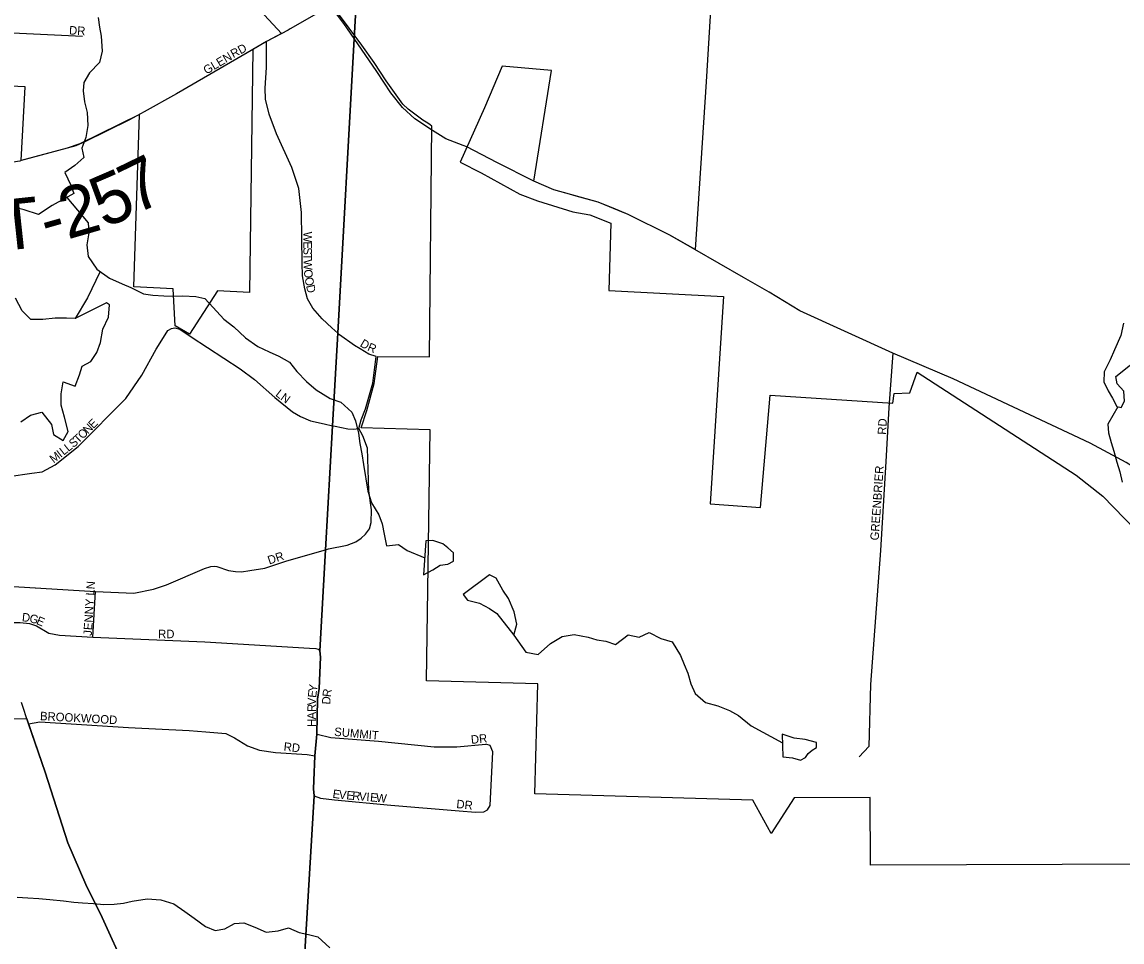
# Model space of a CAD drawing. Extents: x 1759416 to 2214760, y 252598 to 1116833.
# Drawn here: x 1975170 to 1981672, y 856869 to 862305 of the extents above; entities that cross this region are included whole.
import ezdxf

# ---------------------------------------------------------------- set-up
doc = ezdxf.new("R2010")
doc.units = 0
for name, color, linetype in [('GM_X_City_Street', 7, 'Continuous'), ('GM_X_City_Street_Text', 7, 'Continuous'), ('GM_X_Corporation', 7, 'Continuous'), ('GM_X_Minor_Lake', 7, 'Continuous'), ('GM_X_Minor_River', 7, 'Continuous'), ('GM_X_State_Route', 7, 'Continuous'), ('GM_X_Township', 7, 'Continuous'), ('GM_X_Township_Road', 7, 'Continuous'), ('GM_X_Township_Road_Text', 7, 'Continuous'), ('GM_X_Township_Subdivision', 7, 'Continuous'), ('GM_X_Township_Subdivision_Text', 7, 'Continuous')]:
    doc.layers.add(name, color=color, linetype=linetype)

msp = doc.modelspace()

# ---------------------------------------------------------------- linework, layer by layer
at = {"layer": 'GM_X_City_Street'}
for points in [[(1973953.1, 862292.3), (1974040, 862294.5), (1974738, 862257.8), (1975527.8, 862221)], [(1976561.6, 862158.8), (1976083.7, 861881), (1975892.9, 861774.6)], [(1980293.2, 860027.5), (1980293, 860024.4), (1980276.7, 859708.5), (1980244.4, 859182.2), (1980186, 858391.2), (1980175.8, 858023.5), (1980118.3, 857963.8)]]:
    msp.add_lwpolyline(points, dxfattribs=at)
at = {"layer": 'GM_X_Corporation'}
for points in [[(1979325.1, 863774.1), (1979214, 861950.5), (1979148.7, 860960), (1978998.5, 861046.4), (1978752.4, 861168), (1978664.1, 861204.5), (1978575.7, 861241), (1978314.5, 861314), (1978195.4, 861364), (1978300.2, 862018.9), (1978009.2, 862044.1), (1977903, 861797.5), (1977759.1, 861477.3), (1977884.4, 861414.5), (1978113.4, 861287.2), (1978216.3, 861247.5), (1978426.9, 861182.4), (1978527.1, 861165), (1978651.4, 861116.4), (1978637.9, 860718.4), (1979315.7, 860683.9), (1979238.5, 859458.6), (1979535.5, 859436.9), (1979593.2, 860100), (1980317.6, 860053.2), (1980324.8, 860110.9), (1980418.5, 860114.5), (1980461.7, 860237), (1981400.8, 859626.9), (1981558.6, 859504), (1982393.6, 858642)], [(1975947.8, 863054.3), (1976704, 862236.7), (1976615.9, 862190.4), (1976534, 862142.5), (1976515, 860706.8), (1976325.2, 860716.2), (1976159.8, 860460.1), (1976075.7, 860510.4), (1976063.6, 860729), (1975830.9, 860740.8), (1975863.8, 861758.4), (1975511.8, 861584.7), (1975436.8, 861559.6), (1975165.6, 861485.7), (1975189.6, 861922.7), (1973985.8, 861976.4)], [(1981885.6, 857329.1), (1980185.5, 857323.1), (1980184.1, 857723.1), (1979734.1, 857721.5), (1979598.7, 857511.3), (1979488.9, 857707.8), (1978200.9, 857744.3), (1978219.3, 858394.1), (1977561.5, 858412.8), (1977583.2, 859896.1), (1977174.8, 859906.5), (1977208.1, 860010.2), (1977252.1, 860168.8), (1977273, 860329.6), (1977579.4, 860327), (1977592.6, 861689.9), (1977582.3, 861698.2), (1977568.5, 861706.8), (1977539.9, 861725.9), (1977484.5, 861766.6), (1977452.5, 861789.9), (1977420.5, 861820.2), (1977322.3, 861957.4), (1977252.5, 862065.3), (1977179.8, 862167.4), (1976961, 862462.6)], [(1974112.1, 858206.4), (1975198.5, 858187.4), (1975307.5, 857872.5), (1975440.4, 857454.5), (1975548.4, 857209), (1975643.6, 857013.7), (1976064, 856092.6)]]:
    msp.add_lwpolyline(points, dxfattribs=at)
at = {"layer": 'GM_X_Minor_Lake'}
for points in [[(1975484.3, 860552.9), (1975432.3, 860555.2), (1975366.3, 860555.6), (1975294.3, 860548), (1975222.3, 860546.4), (1975170.6, 860598.9), (1975131, 860673.3)], [(1975163.1, 859943.1), (1975221.3, 859982.8), (1975287.4, 860000.5), (1975345, 859925.9), (1975356.7, 859867.7), (1975414.5, 859833.3), (1975442.8, 859885.3), (1975421.2, 859969.6), (1975401.6, 860041.9), (1975402, 860108.1), (1975414.3, 860178.3), (1975484.2, 860153.8), (1975510.5, 860219.8), (1975526.8, 860271.8), (1975576.9, 860299.6), (1975613.2, 860351.6), (1975633.5, 860411.6), (1975647.9, 860489.8), (1975682.3, 860561.8), (1975686.7, 860633.9)], [(1975686.7, 860633.9), (1975668.8, 860645.2), (1975484.3, 860552.9)], [(1981680.8, 860526.3), (1981664.4, 860452.2), (1981628, 860368.2), (1981601.7, 860308.2), (1981567.3, 860238.2), (1981565, 860178), (1981590.7, 860125.7), (1981616.5, 860081.5), (1981642.2, 860033.2), (1981666.2, 860027), (1981686.4, 860065), (1981682.7, 860123.2), (1981642.9, 860167.5), (1981635.2, 860209.7), (1981799.8, 860341.1), (1981842.1, 860399)], [(1977543.9, 859038.5), (1977598, 859068.3), (1977642.1, 859096.1), (1977686.2, 859101.9), (1977720.2, 859119.7), (1977720.5, 859167.9), (1977686.7, 859198.2), (1977656.8, 859222.4), (1977598.9, 859240.8), (1977556.9, 859239)], [(1977556.9, 859239), (1977543.9, 859038.5)], [(1978077.8, 858682.4), (1978094.2, 858746.5), (1978078.6, 858820.8), (1978045, 858899.2), (1978011.3, 858947.5), (1977973.6, 859018), (1977933.8, 859038.3), (1977777.2, 858922.8), (1977803, 858888.6), (1977874.9, 858872.1), (1977932.7, 858839.7), (1977976.5, 858809.4)], [(1977976.5, 858809.4), (1978077.8, 858682.4)], [(1979662.4, 858097.4), (1979667.7, 857963)], [(1979667.7, 857963), (1979723.6, 857956.7), (1979771.6, 857944.4), (1979801.7, 857960.2), (1979817.8, 857982.2), (1979839.9, 858002.1), (1979865.9, 858018), (1979866.1, 858048.1), (1979798.2, 858066.6), (1979734.3, 858073), (1979662.4, 858097.4)]]:
    msp.add_lwpolyline(points, dxfattribs=at)
at = {"layer": 'GM_X_Minor_River'}
for points in [[(1975619.7, 862331.1), (1975627.4, 862274.9), (1975639.1, 862220.6), (1975644.6, 862132.4), (1975628.3, 862066.3), (1975570, 862004.4), (1975535.7, 861948.5), (1975531.4, 861898.4), (1975539.1, 861834.1), (1975554.7, 861769.9), (1975560.3, 861693.6), (1975548, 861623.5), (1975523.6, 861559.5), (1975535.3, 861505.2), (1975483.1, 861457.4), (1975422.9, 861415.7), (1975458.5, 861341.2), (1975476.2, 861291), (1975424.1, 861261.2), (1975347.9, 861221.5), (1975267.6, 861167.9), (1975183.8, 861194.4), (1975109.9, 861212.9)], [(1975434.6, 861267.2), (1975561.3, 861118), (1975565, 861059.8), (1975552.6, 860987.7), (1975562.2, 860919.4), (1975611.8, 860845), (1975687.5, 860792.4), (1975761.3, 860757.8), (1975813.2, 860735.5), (1975889, 860698.9), (1975942.9, 860690.6), (1976008.9, 860686.2), (1976060.9, 860685.9), (1976120.9, 860687.5), (1976196.8, 860683.1), (1976250.8, 860670.7), (1976300.5, 860618.3), (1976364.1, 860549.7), (1976421.8, 860503.2), (1976491.5, 860438.7), (1976563.2, 860388.1), (1976631, 860355.6), (1976688.9, 860331.2), (1976750.7, 860294.7), (1976794.4, 860240.3), (1976852, 860181.8), (1976909.8, 860131.3), (1976991.5, 860080.7), (1977055.3, 860058.3), (1977119, 859999.7), (1977140.8, 859949.5), (1977158.4, 859875.2), (1977168, 859814.9), (1977179.7, 859752.7), (1977189.4, 859690.5), (1977214.5, 859533.9), (1977236.2, 859463.5), (1977279.8, 859393.1), (1977299.5, 859340.8), (1977311.2, 859278.6), (1977324.8, 859210.3), (1977394.8, 859217.9), (1977446.6, 859181.5), (1977550.4, 859138.9)], [(1975631.8, 860831.1), (1975556.9, 860674.8), (1975484.3, 860552.9)], [(1981647.7, 860031.8), (1981587.7, 859929.2), (1981591.4, 859877), (1981607.1, 859820.8), (1981622.8, 859768.6), (1981640.5, 859704.3), (1981658.2, 859648), (1981671.9, 859585.8)], [(1978077.8, 858682.4), (1978147.3, 858581.7), (1978221.2, 858567.2), (1978293.5, 858633), (1978363.7, 858674.7), (1978433.8, 858686.3), (1978515.7, 858669.8), (1978567.6, 858655.5), (1978621.5, 858647.1), (1978677.4, 858626.7), (1978753.7, 858684.4), (1978817.6, 858670), (1978877.8, 858697.8), (1978945.6, 858663.2), (1979013.4, 858642.8), (1979063, 858562.3), (1979084.7, 858508), (1979106.4, 858457.7), (1979124.1, 858395.4), (1979149.8, 858337.1), (1979209.5, 858284.6), (1979283.4, 858264.2), (1979351.2, 858237.7), (1979405, 858207.3), (1979480.7, 858146.7), (1979664.4, 858046.1)], [(1975142.3, 857133.4), (1975204.3, 857131), (1975270.2, 857126.6), (1975334.2, 857120.2), (1975416.1, 857111.7), (1975476.1, 857105.3), (1975528, 857101), (1975592, 857096.6), (1975653.9, 857090.2), (1975715.9, 857091.9), (1975770, 857099.6), (1975822, 857111.3), (1975910.1, 857124.8), (1975990, 857118.3), (1976067.9, 857093.8), (1976133.6, 857049.3), (1976187.4, 857010.9), (1976255.1, 856960.3), (1976311, 856937.9), (1976369, 856947.6), (1976427.2, 856979.4), (1976481.2, 856983.1), (1976547, 856956.6), (1976612.9, 856928.1), (1976684.9, 856935.7), (1976745, 856953.4), (1976808.8, 856925), (1976862.7, 856912.6), (1976918.7, 856900.3), (1976990.3, 856835.7)]]:
    msp.add_lwpolyline(points, dxfattribs=at)
at = {"layer": 'GM_X_State_Route'}
for points in [[(1977777.4, 861576.2), (1977675.6, 861615.2), (1977596.3, 861663.7), (1977492.7, 861733.2), (1977418.9, 861799.4), (1977351.1, 861886.8), (1977267.2, 862012), (1977133.4, 862207.4), (1977072.6, 862296), (1976994.5, 862400.2)], [(1978699.4, 861189.9), (1978575.7, 861241), (1978445.1, 861275.6), (1978405.9, 861287.1), (1978314.5, 861314), (1978195.4, 861364), (1977976.5, 861475.4), (1977799.8, 861567.6), (1977777.4, 861576.2)], [(1983432, 857819.8), (1983196.7, 858095), (1982629.6, 858687.3), (1982162.6, 859201.7), (1981898.6, 859515.9), (1981771.7, 859654.5), (1981696.2, 859703.1), (1981483, 859816.5), (1980673.4, 860197.1), (1980317.2, 860348.3), (1979766.7, 860599.3), (1979585.7, 860708.5), (1979434.5, 860795.4), (1979148, 860960.4), (1978998.5, 861046.4), (1978752.4, 861168), (1978699.4, 861189.9)], [(1976215.8, 855761.2), (1976064, 856092.6), (1975643.6, 857013.7), (1975548.4, 857209), (1975440.4, 857454.5), (1975307.5, 857872.5), (1975207.7, 858159.1), (1975166.6, 858284.8)]]:
    msp.add_lwpolyline(points, dxfattribs=at)
at = {"layer": 'GM_X_Township'}
for points in [[(1977495.1, 869420.8), (1977468.9, 869117.6), (1977456.6, 868931.3), (1977397.8, 868003.6), (1977388.2, 867910.1), (1977396.5, 867802.9), (1977150.5, 862514.3), (1977133.4, 862207.4), (1977036.1, 860466.3), (1977005.6, 859919.9), (1976964.7, 859186.8), (1976931.3, 858590.2), (1976934.2, 858551.6), (1976926.5, 858367.3), (1976916.9, 858304.6), (1976913.8, 858097.3), (1976901.3, 857970.1), (1976894.3, 857823.9), (1976893.3, 857773.7), (1976896.4, 857732.8), (1976716.8, 854704.7)], [(1976716.8, 854704.7), (1976896.4, 857732.8), (1976893.3, 857773.7), (1976894.3, 857823.9), (1976901.3, 857970.1), (1976913.8, 858097.3), (1976916.9, 858304.6), (1976926.5, 858367.3), (1976934.2, 858551.6), (1976931.3, 858590.2), (1976964.7, 859186.8), (1977005.6, 859919.9), (1977036.1, 860466.3), (1977133.4, 862207.4), (1977150.5, 862514.3), (1977396.5, 867802.9), (1977388.2, 867910.1), (1977397.8, 868003.6), (1977456.6, 868931.3), (1977468.9, 869117.6), (1977495.1, 869420.8)]]:
    msp.add_lwpolyline(points, dxfattribs=at)
at = {"layer": 'GM_X_Township_Road'}
for points in [[(1976994.5, 862400.2), (1976755.2, 862263.9)], [(1976755.2, 862263.9), (1976744.1, 862257.6), (1976615.9, 862190.4), (1976561.6, 862158.8)], [(1975892.9, 861774.6), (1975805.8, 861726), (1975542.1, 861596.9), (1975487.8, 861573.5), (1975436.8, 861559.6), (1975180.3, 861489.7)], [(1975180.3, 861489.7), (1975173.8, 861488), (1975165.6, 861485.7), (1975156.9, 861483.4), (1975091.8, 861472), (1974824.9, 861455.7), (1974598.7, 861436.2), (1974139.7, 861385.5)], [(1980317.2, 860348.3), (1980293.2, 860027.5)]]:
    msp.add_lwpolyline(points, dxfattribs=at)
at = {"layer": 'GM_X_Township_Subdivision'}
for points in [[(1977001.3, 860498.7), (1976945, 860551), (1976890.1, 860614.2), (1976856.9, 860670), (1976841.3, 860729.1), (1976827.4, 860805.5), (1976825.6, 860880.1), (1976822.2, 861178.7), (1976806.5, 861321.1), (1976764.9, 861444.4), (1976674.6, 861644), (1976631.5, 861759.8), (1976610.4, 861850), (1976607.5, 861913.4), (1976616.2, 862036.4), (1976615.9, 862190.4)], [(1974660.6, 859541.5), (1974930.7, 859586.9), (1975092.8, 859618.8), (1975228.4, 859640.1), (1975289.5, 859648.1), (1975366.6, 859687.9), (1975502.2, 859796.9), (1975784.6, 860081.4), (1975877.6, 860218.4), (1975964, 860371.3), (1976006.5, 860441.8), (1976031.8, 860481.6), (1976053.1, 860494.9), (1976073, 860498.9), (1976102.2, 860489.6), (1976170.1, 860444.9), (1976460.3, 860255.5), (1976543.5, 860191.8), (1976665.6, 860085.5), (1976770, 860002.3), (1976816.1, 859974), (1976876.2, 859949.2), (1976956.2, 859931.1)], [(1977263.9, 860329.4), (1977219.4, 860342.8), (1977168.7, 860373.9), (1977135.5, 860393.6), (1977047.5, 860455.8), (1977036.1, 860466.3), (1977001.3, 860498.7)], [(1976943.2, 859180.6), (1976964.6, 859186.8), (1976981.2, 859191.5), (1977091.4, 859213.3), (1977143, 859233.1), (1977175.8, 859255.2), (1977201.4, 859278.2), (1977224.4, 859310.9), (1977234.2, 859347.2), (1977235.9, 859423.3), (1977221.1, 859534.8), (1977212, 859787.7), (1977184.6, 859859.8), (1977161.6, 859903.2), (1977175.8, 859953.6), (1977199.7, 860019.1), (1977243.2, 860171.9), (1977263.9, 860329.4)], [(1976956.2, 859931.1), (1977005.6, 859919.9), (1977020.9, 859916.5), (1977095.3, 859900.5), (1977129.7, 859898.8), (1977161.6, 859903.2)], [(1974891.9, 858983.7), (1975605.4, 858940.6), (1975831.7, 858929.8), (1975948.1, 858953.6), (1976023.6, 858979.4), (1976248.3, 859076), (1976286.4, 859087.8), (1976305.4, 859089.3), (1976322.5, 859087.5), (1976390.1, 859065.2), (1976431.5, 859058.3), (1976467, 859057.2), (1976516.4, 859065.2), (1976604.8, 859079), (1976728.8, 859119.2), (1976943.2, 859180.6)], [(1975588.1, 858671.1), (1975605.4, 858940.6)], [(1974982.4, 858757.3), (1975159.2, 858757.3), (1975215.2, 858750.9), (1975256.2, 858737.9), (1975329.5, 858694.8), (1975392, 858681.9), (1975588.1, 858671.1), (1976249.9, 858643.1), (1976869.6, 858605.7), (1976906.3, 858602.8), (1976921.7, 858598.9), (1976931.3, 858590.2), (1976934.2, 858551.6)], [(1976896.4, 857732.8), (1976893.3, 857773.7), (1976894.3, 857823.9), (1976901.3, 857970.1), (1976913.9, 858097.3), (1976916.9, 858304.6), (1976926.5, 858367.3), (1976934.2, 858551.6)], [(1975207.7, 858159.1), (1975275.8, 858170.2), (1975799.8, 858137), (1976157.5, 858119.5), (1976257.2, 858110.1), (1976375.9, 858102.1), (1976426.6, 858075.2), (1976503.9, 858029.2), (1976573.8, 858002.6), (1976668.3, 857989.3), (1976855.6, 857977.8), (1976901.3, 857970.1)], [(1976913.9, 858097.3), (1976995.2, 858078.5), (1977276.7, 858055.6), (1977605.8, 858023.2), (1977740.1, 858023.2), (1977911.2, 858038.2)], [(1977900.3, 857639.3), (1977922.1, 857650.4), (1977936.6, 857676.4), (1977953.9, 857992.8), (1977936.6, 858030.4), (1977911.2, 858038.2)], [(1976896.4, 857732.8), (1976934.1, 857718.2), (1977017.8, 857708.8), (1977350.6, 857677.4), (1977753.9, 857645.2), (1977850.7, 857636.7), (1977900.3, 857639.3)]]:
    msp.add_lwpolyline(points, dxfattribs=at)

# ---------------------------------------------------------------- texts
at = {"layer": 'GM_X_City_Street_Text'}
for s, rotation, p in [('DR', 356.82219, (1975447.3, 862232)), ('GLEN', 30.69988, (1976260.4, 861993.8)), ('RD', 27.9014, (1976419.2, 862090.8)), ('RD', 86.98841, (1980277.4, 859865.4)), ('GREENBRIER', 86.05454, (1980233.4, 859240.7))]:
    msp.add_text(s, height=50, rotation=rotation, dxfattribs=at).set_placement(p)
at = {"layer": 'GM_X_Township_Road_Text'}
for s, rotation, p in [('7', 25.83559, (1975838.1, 861163.5)), ('5', 23.34867, (1975655.6, 861084.3)), ('2', 16.06709, (1975438.9, 861019.2)), ('T', 6.13574, (1975041.7, 860950.6)), ('-', 15.85913, (1975319.2, 860985.2))]:
    msp.add_text(s, height=300, rotation=rotation, dxfattribs=at).set_placement(p)
at = {"layer": 'GM_X_Township_Subdivision_Text'}
for s, rotation, p in [('W', 270.11769, (1976833.4, 861066)), ('S', 270.09545, (1976833.6, 860973.7)), ('E', 270.1093, (1976833.5, 861008.8)), ('T', 270.1093, (1976833.6, 860938.5)), ('W', 271.8579, (1976833.7, 860901.6)), ('O', 275.42568, (1976835.8, 860841.1)), ('O', 279.56637, (1976840.5, 860793.3)), ('D', 283.58369, (1976848.6, 860746.2)), ('D', 329.05124, (1977163.8, 860391.8)), ('R', 336.43771, (1977207.7, 860366)), ('L', 321.87346, (1976664.6, 860099.3)), ('N', 324.33133, (1976694.1, 860076.2)), ('N', 44.99921, (1975560.1, 859868.3)), ('E', 45, (1975591.2, 859899.4)), ('S', 39.8191, (1975473, 859786.9)), ('T', 44.10562, (1975503.1, 859812.1)), ('O', 44.9833, (1975529, 859837.2)), ('I', 38.05901, (1975399, 859728.8)), ('L', 38.05211, (1975416.3, 859742.4)), ('L', 38.02833, (1975444, 859764.1)), ('M', 38.0539, (1975357.4, 859696.3)), ('DR', 18.43495, (1976631.8, 859099.4)), ('JENNY LN', 86.53356, (1975582.6, 858677.4)), ('D', 354.79172, (1975168.4, 858764.5)), ('G', 344.62797, (1975209.9, 858760.9)), ('E', 336.8337, (1975250.6, 858749.8)), ('RD', 0.00001, (1975974.8, 858664.3)), ('E', 83.56628, (1976908.5, 858310.2)), ('Y', 82.59308, (1976912.4, 858344.9)), ('R', 82.25451, (1976994.7, 858314.2)), ('V', 88.11996, (1976907.1, 858267.2)), ('D', 86.39093, (1976992, 858271.3)), ('BROOKWOOD', 356.92431, (1975275.7, 858180.3)), ('A', 89.93441, (1976907, 858184.1)), ('R', 89.92712, (1976907.1, 858228)), ('H', 89.93441, (1976907, 858140.1)), ('SUMMIT', 354.9006, (1977014, 858087.9)), ('DR', 6.00541, (1977826.2, 858039.5)), ('RD', 353.99339, (1976715, 857999.8)), ('E', 351.33278, (1977003.5, 857722.1)), ('V', 354.85922, (1977041.5, 857716.4)), ('E', 355.10625, (1977085.6, 857712.5)), ('R', 355.08916, (1977120.6, 857709.5)), ('V', 355.09837, (1977160.1, 857706.1)), ('I', 355.11742, (1977204, 857702.3)), ('E', 355.1048, (1977225.9, 857700.4)), ('W', 355.10091, (1977261, 857697.4)), ('DR', 353.99459, (1977735.8, 857661))]:
    msp.add_text(s, height=50, rotation=rotation, dxfattribs=at).set_placement(p)

doc.saveas('drawing.dxf')
